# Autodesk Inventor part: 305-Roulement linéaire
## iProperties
Author: Philippe
Created: 2001-12
Part Number: 305-Roulement linéaire
Material: Par défaut
Document SubType Name: Modélisation
Designer: Philippe
Control State: 0
Master: False
Checked Out: False
PropertySet Name: Design Tracking Control
Shininess: 60.0
Angle Display Precision: 2
Document Length Units: 11269
Document Angle Units: 11283
Document Time Units: 11279
Document Mass Units: 11290
Document Length Units Precision: 3
Document Angle Units Precision: 2
Compacted: False
PropertySet Name: _Private Model Information
Density: 0.0
Volumn: 0.0
Area: 0.0
PropertySet Name: Model Information
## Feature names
1. Extrusion1
2. Extrusion2
3. Extrusion3
4. Perçage1 [Hole]
5. Chanfrein1 [Chamfer]
